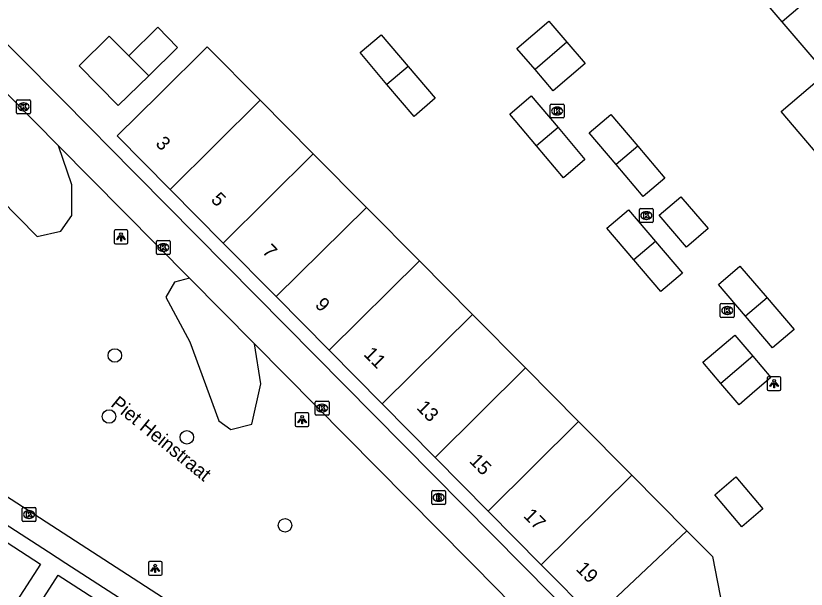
# Model space of a CAD drawing. Extents: x 160379 to 161131, y 383940 to 384849.
# Drawn here: x 160708.7 to 160765.9, y 384576.8 to 384618.3 of the extents above; entities that cross this region are included whole.
import ezdxf

# ---------------------------------------------------------------- set-up
doc = ezdxf.new("R2010")
doc.units = 0
for name, color, linetype in [('IMGEO_Boom', 7, 'Continuous'), ('IMGEO_Brandkraan', 7, 'Continuous'), ('IMGEO_Groenvoorziening', 7, 'Continuous'), ('IMGEO_Kolk', 7, 'Continuous'), ('IMGEO_Lichtpunt', 7, 'Continuous'), ('IMGEO_Openbare_ruimte_label', 7, 'Continuous'), ('IMGEO_Pand', 7, 'Continuous'), ('IMGEO_Pand_nummerreeks', 7, 'Continuous'), ('IMGEO_Voetgangersgebied_open', 7, 'Continuous')]:
    doc.layers.add(name, color=color, linetype=linetype)

msp = doc.modelspace()

# ---------------------------------------------------------------- linework, layer by layer
at = {"layer": 'IMGEO_Boom'}
for centre in [(160715.854, 384593.757), (160715.439, 384589.341), (160721.065, 384587.835), (160728.176, 384581.465)]:
    msp.add_circle(centre, 0.489, dxfattribs=at)
at = {"layer": 'IMGEO_Brandkraan'}
for p, q in [((160738.796, 384583.058), (160738.796, 384583.91)), ((160738.871, 384583.984), (160739.723, 384583.984)), ((160739.284, 384583.764), (160739.309, 384583.764)), ((160739.797, 384583.91), (160739.797, 384583.058)), ((160739.723, 384582.984), (160738.871, 384582.984)), ((160739.307, 384583.204), (160739.282, 384583.204))]:
    msp.add_line(p, q, dxfattribs=at)
for points in [[(160738.796, 384583.058), (160738.796, 384583.91)], [(160738.871, 384583.984), (160739.723, 384583.984)], [(160739.144, 384583.684), (160739.144, 384583.284), (160739.357, 384583.284)], [(160739.375, 384583.684), (160739.144, 384583.684)], [(160739.323, 384583.603), (160739.269, 384583.603), (160739.269, 384583.527)], [(160739.797, 384583.91), (160739.797, 384583.058)], [(160739.723, 384582.984), (160738.871, 384582.984)], [(160739.269, 384583.527), (160739.322, 384583.527)], [(160739.331, 384583.451), (160739.269, 384583.451), (160739.269, 384583.37)], [(160739.269, 384583.37), (160739.331, 384583.37)]]:
    msp.add_lwpolyline(points, dxfattribs=at)
for centre, radius, start, end in [((160738.873, 384583.908), 0.0765, 91.552, 178.448), ((160738.873, 384583.908), 0.0765, 91.552, 178.448), ((160739.324, 384583.565), 0.0379, 267.8285, 90.9355), ((160739.379, 384583.539), 0.145, 59.4692, 91.5367), ((160739.404, 384583.586), 0.0922, 285.5137, 58.1501), ((160739.721, 384583.908), 0.0765, 1.552, 88.448), ((160739.721, 384583.908), 0.0765, 1.552, 88.448), ((160738.873, 384583.06), 0.0765, 181.552, 268.448), ((160738.873, 384583.06), 0.0765, 181.552, 268.448), ((160739.332, 384583.41), 0.0404, 269.8759, 90.5077), ((160739.363, 384583.535), 0.251, 268.6676, 293.5347), ((160739.409, 384583.394), 0.105, 301.3115, 78.989), ((160739.721, 384583.06), 0.0765, 271.552, 358.448), ((160739.721, 384583.06), 0.0765, 271.552, 358.448)]:
    msp.add_arc(centre, radius, start, end, dxfattribs=at)
for centre, major_axis, ratio, start_param, end_param in [((160739.283, 384583.484), (-0.387, 0.002), 0.722429, 4.712389, 7.853982), ((160739.308, 384583.484), (-0.39, 0.002), 0.717154, 1.570796, 4.712389)]:
    msp.add_ellipse(centre, major_axis=major_axis, ratio=ratio, start_param=start_param, end_param=end_param, dxfattribs=at)
at = {"layer": 'IMGEO_Groenvoorziening'}
for points in [[(160699.59, 384611.514), (160701.271, 384608.535), (160703.61, 384607.511), (160707.527, 384605.097), (160710.224, 384602.36), (160711.951, 384602.741), (160712.738, 384603.874), (160712.736, 384606.095), (160711.786, 384608.924)], [(160721.26, 384599.354), (160720.165, 384599.054), (160719.537, 384597.985), (160721.297, 384594.737), (160723.391, 384589.033), (160724.263, 384588.408), (160725.779, 384588.784), (160726.437, 384591.692), (160725.963, 384594.603)]]:
    msp.add_lwpolyline(points, dxfattribs=at)
at = {"layer": 'IMGEO_Kolk'}
for p, q in [((160708.746, 384611.318), (160708.746, 384612.17)), ((160708.821, 384612.244), (160709.673, 384612.244)), ((160709.747, 384612.17), (160709.747, 384611.318)), ((160709.234, 384612.024), (160709.259, 384612.024)), ((160747.372, 384611.012), (160747.372, 384611.864)), ((160747.447, 384611.938), (160748.299, 384611.938)), ((160747.86, 384611.718), (160747.885, 384611.718)), ((160748.373, 384611.864), (160748.373, 384611.012)), ((160709.673, 384611.244), (160708.821, 384611.244)), ((160709.257, 384611.464), (160709.232, 384611.464)), ((160747.883, 384611.158), (160747.858, 384611.158)), ((160748.299, 384610.938), (160747.447, 384610.938)), ((160753.829, 384603.451), (160753.829, 384604.303)), ((160753.904, 384604.377), (160754.756, 384604.377)), ((160754.317, 384604.157), (160754.342, 384604.157)), ((160754.83, 384604.303), (160754.83, 384603.451)), ((160754.34, 384603.597), (160754.315, 384603.597)), ((160754.756, 384603.377), (160753.904, 384603.377)), ((160718.863, 384601.136), (160718.863, 384601.988)), ((160718.938, 384602.062), (160719.79, 384602.062)), ((160719.864, 384601.988), (160719.864, 384601.136)), ((160719.374, 384601.282), (160719.349, 384601.282)), ((160719.351, 384601.842), (160719.376, 384601.842)), ((160719.79, 384601.062), (160718.938, 384601.062)), ((160759.684, 384596.582), (160759.684, 384597.434)), ((160759.759, 384597.508), (160760.611, 384597.508)), ((160760.172, 384597.288), (160760.197, 384597.288)), ((160760.685, 384597.434), (160760.685, 384596.582)), ((160760.195, 384596.728), (160760.17, 384596.728)), ((160760.611, 384596.508), (160759.759, 384596.508)), ((160730.436, 384590.443), (160731.288, 384590.443)), ((160730.361, 384589.517), (160730.361, 384590.369)), ((160730.849, 384590.223), (160730.874, 384590.223)), ((160731.362, 384590.369), (160731.362, 384589.517)), ((160731.288, 384589.443), (160730.436, 384589.443)), ((160730.872, 384589.663), (160730.847, 384589.663)), ((160709.148, 384581.825), (160709.148, 384582.677)), ((160709.223, 384582.751), (160710.075, 384582.751)), ((160709.636, 384582.531), (160709.661, 384582.531)), ((160710.149, 384582.677), (160710.149, 384581.825)), ((160709.659, 384581.971), (160709.634, 384581.971)), ((160710.075, 384581.751), (160709.223, 384581.751))]:
    msp.add_line(p, q, dxfattribs=at)
for points in [[(160708.746, 384611.318), (160708.746, 384612.17)], [(160708.821, 384612.244), (160709.673, 384612.244)], [(160709.747, 384612.17), (160709.747, 384611.318)], [(160709.067, 384611.944), (160709.19, 384611.944), (160709.19, 384611.793), (160709.32, 384611.944), (160709.484, 384611.944), (160709.338, 384611.793), (160709.491, 384611.544), (160709.339, 384611.544), (160709.254, 384611.708), (160709.19, 384611.641), (160709.19, 384611.544), (160709.067, 384611.544), (160709.067, 384611.944)], [(160747.372, 384611.012), (160747.372, 384611.864)], [(160747.447, 384611.938), (160748.299, 384611.938)], [(160747.693, 384611.638), (160747.816, 384611.638), (160747.816, 384611.487), (160747.946, 384611.638), (160748.11, 384611.638), (160747.964, 384611.487), (160748.117, 384611.238), (160747.965, 384611.238), (160747.88, 384611.402), (160747.816, 384611.335), (160747.816, 384611.238), (160747.693, 384611.238), (160747.693, 384611.638)], [(160748.373, 384611.864), (160748.373, 384611.012)], [(160709.673, 384611.244), (160708.821, 384611.244)], [(160748.299, 384610.938), (160747.447, 384610.938)], [(160753.829, 384603.451), (160753.829, 384604.303)], [(160753.904, 384604.377), (160754.756, 384604.377)], [(160754.83, 384604.303), (160754.83, 384603.451)], [(160754.15, 384604.077), (160754.273, 384604.077), (160754.273, 384603.926), (160754.403, 384604.077), (160754.567, 384604.077), (160754.421, 384603.926), (160754.574, 384603.677), (160754.422, 384603.677), (160754.337, 384603.841), (160754.273, 384603.774), (160754.273, 384603.677), (160754.15, 384603.677), (160754.15, 384604.077)], [(160754.756, 384603.377), (160753.904, 384603.377)], [(160718.863, 384601.136), (160718.863, 384601.988)], [(160718.938, 384602.062), (160719.79, 384602.062)], [(160719.864, 384601.988), (160719.864, 384601.136)], [(160719.184, 384601.762), (160719.307, 384601.762), (160719.307, 384601.611), (160719.437, 384601.762), (160719.601, 384601.762), (160719.455, 384601.611), (160719.608, 384601.362), (160719.456, 384601.362), (160719.371, 384601.526), (160719.307, 384601.459), (160719.307, 384601.362), (160719.184, 384601.362), (160719.184, 384601.762)], [(160719.79, 384601.062), (160718.938, 384601.062)], [(160759.684, 384596.582), (160759.684, 384597.434)], [(160759.759, 384597.508), (160760.611, 384597.508)], [(160760.685, 384597.434), (160760.685, 384596.582)], [(160760.005, 384597.208), (160760.128, 384597.208), (160760.128, 384597.057), (160760.258, 384597.208), (160760.422, 384597.208), (160760.276, 384597.057), (160760.429, 384596.808), (160760.277, 384596.808), (160760.192, 384596.972), (160760.128, 384596.905), (160760.128, 384596.808), (160760.005, 384596.808), (160760.005, 384597.208)], [(160760.611, 384596.508), (160759.759, 384596.508)], [(160730.436, 384590.443), (160731.288, 384590.443)], [(160730.361, 384589.517), (160730.361, 384590.369)], [(160730.682, 384590.143), (160730.805, 384590.143), (160730.805, 384589.992), (160730.935, 384590.143), (160731.099, 384590.143), (160730.953, 384589.992), (160731.106, 384589.743), (160730.954, 384589.743), (160730.869, 384589.907), (160730.805, 384589.84), (160730.805, 384589.743), (160730.682, 384589.743), (160730.682, 384590.143)], [(160731.362, 384590.369), (160731.362, 384589.517)], [(160731.288, 384589.443), (160730.436, 384589.443)], [(160709.148, 384581.825), (160709.148, 384582.677)], [(160709.223, 384582.751), (160710.075, 384582.751)], [(160709.469, 384582.451), (160709.592, 384582.451), (160709.592, 384582.3), (160709.722, 384582.451), (160709.886, 384582.451), (160709.74, 384582.3), (160709.893, 384582.051), (160709.741, 384582.051), (160709.656, 384582.215), (160709.592, 384582.148), (160709.592, 384582.051), (160709.469, 384582.051), (160709.469, 384582.451)], [(160710.149, 384582.677), (160710.149, 384581.825)], [(160710.075, 384581.751), (160709.223, 384581.751)]]:
    msp.add_lwpolyline(points, dxfattribs=at)
for centre, start, end in [((160708.823, 384612.168), 91.552, 178.448), ((160708.823, 384612.168), 91.552, 178.448), ((160709.671, 384612.168), 1.552, 88.448), ((160709.671, 384612.168), 1.552, 88.448), ((160747.449, 384611.862), 91.552, 178.448), ((160747.449, 384611.862), 91.552, 178.448), ((160748.297, 384611.862), 1.552, 88.448), ((160748.297, 384611.862), 1.552, 88.448), ((160708.823, 384611.32), 181.552, 268.448), ((160708.823, 384611.32), 181.552, 268.448), ((160709.671, 384611.32), 271.552, 358.448), ((160709.671, 384611.32), 271.552, 358.448), ((160747.449, 384611.014), 181.552, 268.448), ((160747.449, 384611.014), 181.552, 268.448), ((160748.297, 384611.014), 271.552, 358.448), ((160748.297, 384611.014), 271.552, 358.448), ((160753.906, 384604.301), 91.552, 178.448), ((160753.906, 384604.301), 91.552, 178.448), ((160754.754, 384604.301), 1.552, 88.448), ((160754.754, 384604.301), 1.552, 88.448), ((160753.906, 384603.453), 181.552, 268.448), ((160753.906, 384603.453), 181.552, 268.448), ((160754.754, 384603.453), 271.552, 358.448), ((160754.754, 384603.453), 271.552, 358.448), ((160718.94, 384601.986), 91.552, 178.448), ((160718.94, 384601.986), 91.552, 178.448), ((160719.788, 384601.986), 1.552, 88.448), ((160719.788, 384601.986), 1.552, 88.448), ((160718.94, 384601.138), 181.552, 268.448), ((160718.94, 384601.138), 181.552, 268.448), ((160719.788, 384601.138), 271.552, 358.448), ((160719.788, 384601.138), 271.552, 358.448), ((160759.761, 384597.432), 91.552, 178.448), ((160759.761, 384597.432), 91.552, 178.448), ((160760.609, 384597.432), 1.552, 88.448), ((160760.609, 384597.432), 1.552, 88.448), ((160759.761, 384596.584), 181.552, 268.448), ((160759.761, 384596.584), 181.552, 268.448), ((160760.609, 384596.584), 271.552, 358.448), ((160760.609, 384596.584), 271.552, 358.448), ((160730.438, 384590.367), 91.552, 178.448), ((160730.438, 384590.367), 91.552, 178.448), ((160731.286, 384590.367), 1.552, 88.448), ((160731.286, 384590.367), 1.552, 88.448), ((160730.438, 384589.519), 181.552, 268.448), ((160730.438, 384589.519), 181.552, 268.448), ((160731.286, 384589.519), 271.552, 358.448), ((160731.286, 384589.519), 271.552, 358.448), ((160709.225, 384582.675), 91.552, 178.448), ((160709.225, 384582.675), 91.552, 178.448), ((160710.073, 384582.675), 1.552, 88.448), ((160710.073, 384582.675), 1.552, 88.448), ((160709.225, 384581.827), 181.552, 268.448), ((160709.225, 384581.827), 181.552, 268.448), ((160710.073, 384581.827), 271.552, 358.448), ((160710.073, 384581.827), 271.552, 358.448)]:
    msp.add_arc(centre, 0.0765, start, end, dxfattribs=at)
for centre, major_axis, ratio, start_param, end_param in [((160709.233, 384611.744), (-0.387, 0.002), 0.722429, 4.712389, 7.853982), ((160709.258, 384611.744), (-0.39, 0.002), 0.717154, 1.570796, 4.712389), ((160747.859, 384611.438), (-0.387, 0.002), 0.722429, 4.712389, 7.853982), ((160747.884, 384611.438), (-0.39, 0.002), 0.717154, 1.570796, 4.712389), ((160754.316, 384603.877), (-0.387, 0.002), 0.722429, 4.712389, 7.853982), ((160754.341, 384603.877), (-0.39, 0.002), 0.717154, 1.570796, 4.712389), ((160719.35, 384601.562), (-0.387, 0.002), 0.722429, 4.712389, 7.853982), ((160719.375, 384601.562), (-0.39, 0.002), 0.717154, 1.570796, 4.712389), ((160760.171, 384597.008), (-0.387, 0.002), 0.722429, 4.712389, 7.853982), ((160760.196, 384597.008), (-0.39, 0.002), 0.717154, 1.570796, 4.712389), ((160730.848, 384589.943), (-0.387, 0.002), 0.722429, 4.712389, 7.853982), ((160730.873, 384589.943), (-0.39, 0.002), 0.717154, 1.570796, 4.712389), ((160709.635, 384582.251), (-0.387, 0.002), 0.722429, 4.712389, 7.853982), ((160709.66, 384582.251), (-0.39, 0.002), 0.717154, 1.570796, 4.712389)]:
    msp.add_ellipse(centre, major_axis=major_axis, ratio=ratio, start_param=start_param, end_param=end_param, dxfattribs=at)
at = {"layer": 'IMGEO_Lichtpunt'}
for p, q in [((160715.805, 384602.738), (160715.805, 384601.931)), ((160715.805, 384602.738), (160715.805, 384601.931)), ((160716.707, 384602.833), (160715.899, 384602.833)), ((160716.707, 384602.833), (160715.899, 384602.833)), ((160716.801, 384601.931), (160716.801, 384602.738)), ((160716.801, 384601.931), (160716.801, 384602.738)), ((160715.899, 384601.837), (160716.707, 384601.837)), ((160715.899, 384601.837), (160716.707, 384601.837)), ((160763.077, 384592.126), (160763.077, 384591.319)), ((160763.077, 384592.126), (160763.077, 384591.319)), ((160763.979, 384592.221), (160763.171, 384592.221)), ((160763.979, 384592.221), (160763.171, 384592.221)), ((160764.073, 384591.319), (160764.073, 384592.126)), ((160764.073, 384591.319), (160764.073, 384592.126)), ((160763.171, 384591.225), (160763.979, 384591.225)), ((160763.171, 384591.225), (160763.979, 384591.225)), ((160728.914, 384589.512), (160728.914, 384588.705)), ((160728.914, 384589.512), (160728.914, 384588.705)), ((160729.816, 384589.607), (160729.008, 384589.607)), ((160729.816, 384589.607), (160729.008, 384589.607)), ((160729.91, 384588.705), (160729.91, 384589.512)), ((160729.91, 384588.705), (160729.91, 384589.512)), ((160729.008, 384588.611), (160729.816, 384588.611)), ((160729.008, 384588.611), (160729.816, 384588.611)), ((160718.284, 384578.753), (160718.284, 384577.946)), ((160718.284, 384578.753), (160718.284, 384577.946)), ((160719.186, 384578.848), (160718.378, 384578.848)), ((160719.186, 384578.848), (160718.378, 384578.848)), ((160719.28, 384577.946), (160719.28, 384578.753)), ((160719.28, 384577.946), (160719.28, 384578.753)), ((160718.378, 384577.852), (160719.186, 384577.852)), ((160718.378, 384577.852), (160719.186, 384577.852))]:
    msp.add_line(p, q, dxfattribs=at)
for points in [[(160716.179, 384602.402), (160716.218, 384602.374), (160716.03, 384602.112), (160715.992, 384602.139), (160716.179, 384602.402)], [(160716.281, 384602.354), (160716.328, 384602.354), (160716.328, 384602.032), (160716.281, 384602.032), (160716.281, 384602.354)], [(160716.391, 384602.374), (160716.429, 384602.401), (160716.616, 384602.139), (160716.577, 384602.111), (160716.391, 384602.374)], [(160763.451, 384591.79), (160763.49, 384591.762), (160763.302, 384591.5), (160763.264, 384591.527), (160763.451, 384591.79)], [(160763.553, 384591.742), (160763.6, 384591.742), (160763.6, 384591.42), (160763.553, 384591.42), (160763.553, 384591.742)], [(160763.663, 384591.762), (160763.701, 384591.789), (160763.888, 384591.527), (160763.849, 384591.499), (160763.663, 384591.762)], [(160729.288, 384589.176), (160729.327, 384589.148), (160729.139, 384588.886), (160729.101, 384588.913), (160729.288, 384589.176)], [(160729.39, 384589.128), (160729.437, 384589.128), (160729.437, 384588.806), (160729.39, 384588.806), (160729.39, 384589.128)], [(160729.5, 384589.148), (160729.538, 384589.175), (160729.725, 384588.913), (160729.686, 384588.885), (160729.5, 384589.148)], [(160718.658, 384578.417), (160718.697, 384578.389), (160718.509, 384578.127), (160718.471, 384578.154), (160718.658, 384578.417)], [(160718.87, 384578.389), (160718.908, 384578.416), (160719.095, 384578.154), (160719.056, 384578.126), (160718.87, 384578.389)], [(160718.76, 384578.369), (160718.807, 384578.369), (160718.807, 384578.047), (160718.76, 384578.047), (160718.76, 384578.369)]]:
    msp.add_lwpolyline(points, dxfattribs=at)
for centre in [(160716.304, 384602.536), (160763.576, 384591.924), (160729.413, 384589.31), (160718.783, 384578.551)]:
    msp.add_circle(centre, 0.0994, dxfattribs=at)
for centre, start, end in [((160715.899, 384602.738), 90, 180), ((160715.899, 384602.738), 90, 180), ((160716.707, 384602.738), 0, 90), ((160716.707, 384602.738), 0, 90), ((160715.899, 384601.931), 180, 270), ((160715.899, 384601.931), 180, 270), ((160716.707, 384601.931), 270, 0), ((160716.707, 384601.931), 270, 360), ((160763.171, 384592.126), 90, 180), ((160763.171, 384592.126), 90, 180), ((160763.979, 384592.126), 0, 90), ((160763.979, 384592.126), 0, 90), ((160763.171, 384591.319), 180, 270), ((160763.171, 384591.319), 180, 270), ((160763.979, 384591.319), 270, 0), ((160763.979, 384591.319), 270, 360), ((160729.008, 384589.512), 90, 180), ((160729.008, 384589.512), 90, 180), ((160729.816, 384589.512), 0, 90), ((160729.816, 384589.512), 0, 90), ((160729.008, 384588.705), 180, 270), ((160729.008, 384588.705), 180, 270), ((160729.816, 384588.705), 270, 0), ((160729.816, 384588.705), 270, 360), ((160718.378, 384578.753), 90, 180), ((160718.378, 384578.753), 90, 180), ((160719.186, 384578.753), 0, 90), ((160719.186, 384578.753), 0, 90), ((160718.378, 384577.946), 180, 270), ((160718.378, 384577.946), 180, 270), ((160719.186, 384577.946), 270, 0), ((160719.186, 384577.946), 270, 360)]:
    msp.add_arc(centre, 0.0946, start, end, dxfattribs=at)
at = {"layer": 'IMGEO_Pand'}
for points in [[(160771.144, 384623.858), (160764.164, 384617.895)], [(160764.164, 384617.895), (160760.992, 384621.608)], [(160746.278, 384614.432), (160744.967, 384615.96), (160747.272, 384617.93), (160748.582, 384616.409)], [(160767.337, 384614.183), (160764.164, 384617.895)], [(160716.859, 384615.44), (160718.967, 384617.515), (160720.405, 384616.026), (160718.308, 384613.978)], [(160718.308, 384613.978), (160716.107, 384611.828), (160713.265, 384614.708), (160715.451, 384616.86), (160716.859, 384615.44)], [(160735.557, 384613.361), (160733.604, 384615.665), (160735.13, 384616.962), (160737.087, 384614.663)], [(160748.582, 384616.409), (160749.904, 384614.874), (160747.588, 384612.904), (160746.278, 384614.432)], [(160748.582, 384616.409), (160746.278, 384614.432)], [(160719.863, 384605.769), (160716.028, 384609.647), (160719.085, 384612.663), (160722.549, 384616.082), (160726.383, 384612.216)], [(160718.308, 384613.978), (160716.859, 384615.44)], [(160737.087, 384614.663), (160739.043, 384612.364), (160737.515, 384611.052), (160735.557, 384613.361)], [(160737.087, 384614.663), (160735.557, 384613.361)], [(160770.509, 384610.47), (160767.258, 384607.692), (160764.086, 384611.405), (160767.337, 384614.183)], [(160726.383, 384612.216), (160719.863, 384605.769)], [(160726.383, 384612.216), (160730.224, 384608.344)], [(160746.387, 384608.916), (160744.444, 384611.216), (160746.002, 384612.544), (160747.95, 384610.236)], [(160752.148, 384607.561), (160750.197, 384609.852), (160751.77, 384611.183), (160753.715, 384608.887)], [(160747.95, 384610.236), (160749.89, 384607.937), (160748.329, 384606.615), (160746.387, 384608.916)], [(160747.95, 384610.236), (160746.387, 384608.916)], [(160753.715, 384608.887), (160755.659, 384606.591), (160754.102, 384605.266), (160752.148, 384607.561)], [(160753.715, 384608.887), (160752.148, 384607.561)], [(160730.224, 384608.344), (160723.699, 384601.891)], [(160730.224, 384608.344), (160734.065, 384604.471)], [(160723.699, 384601.891), (160719.863, 384605.769)], [(160757.237, 384601.601), (160755.262, 384603.909), (160756.827, 384605.239), (160758.801, 384602.944), (160757.237, 384601.601)], [(160734.065, 384604.471), (160727.534, 384598.012)], [(160734.065, 384604.471), (160737.906, 384600.598)], [(160753.425, 384600.664), (160751.467, 384602.955), (160753.035, 384604.29), (160754.989, 384601.996)], [(160727.534, 384598.012), (160723.699, 384601.891)], [(160754.989, 384601.996), (160756.943, 384599.702), (160755.374, 384598.382), (160753.425, 384600.664)], [(160754.989, 384601.996), (160753.425, 384600.664)], [(160737.906, 384600.598), (160731.369, 384594.134)], [(160737.906, 384600.598), (160741.747, 384596.726)], [(160761.511, 384596.596), (160759.548, 384598.892), (160761.105, 384600.22), (160763.068, 384597.931)], [(160731.369, 384594.134), (160727.534, 384598.012)], [(160763.068, 384597.931), (160765.031, 384595.641), (160763.472, 384594.303), (160761.511, 384596.596)], [(160763.068, 384597.931), (160761.511, 384596.596)], [(160741.747, 384596.726), (160735.205, 384590.256)], [(160741.747, 384596.726), (160745.588, 384592.853)], [(160759.733, 384591.728), (160758.413, 384593.263), (160760.742, 384595.23), (160762.047, 384593.696)], [(160735.205, 384590.256), (160731.369, 384594.134)], [(160762.047, 384593.696), (160763.351, 384592.163), (160762.186, 384591.163), (160761.054, 384590.192), (160759.733, 384591.728)], [(160762.047, 384593.696), (160759.733, 384591.728)], [(160745.588, 384592.853), (160739.04, 384586.378)], [(160745.588, 384592.853), (160749.429, 384588.98)], [(160739.04, 384586.378), (160735.205, 384590.256)], [(160749.429, 384588.98), (160742.875, 384582.499)], [(160749.429, 384588.98), (160753.269, 384585.108)], [(160742.875, 384582.499), (160739.04, 384586.378)], [(160753.269, 384585.108), (160746.711, 384578.621)], [(160753.269, 384585.108), (160757.263, 384581.081)], [(160762.775, 384582.671), (160761.239, 384581.355), (160759.279, 384583.664), (160760.809, 384584.964), (160762.775, 384582.671)], [(160746.711, 384578.621), (160742.875, 384582.499)], [(160706.03, 384581.538), (160710.479, 384578.651), (160705.488, 384570.959), (160701.041, 384573.844)], [(160757.263, 384581.081), (160750.546, 384574.743)], [(160757.263, 384581.081), (160759.108, 384579.223), (160760.561, 384571.796)], [(160750.546, 384574.743), (160746.711, 384578.621)], [(160711.594, 384567.052), (160710.943, 384566.044), (160709.378, 384563.379), (160704.454, 384566.424), (160706.129, 384569.152), (160706.762, 384570.133), (160711.753, 384577.864), (160716.569, 384574.755)]]:
    msp.add_lwpolyline(points, dxfattribs=at)
at = {"layer": 'IMGEO_Voetgangersgebied_open'}
for points in [[(160759.828, 384522.305), (160755.906, 384542.287), (160755.616, 384543.763), (160752.301, 384560.653), (160749.625, 384574.277), (160715.318, 384608.946), (160714.28, 384609.995), (160704.012, 384620.371), (160696.715, 384627.735), (160696.648, 384627.802)], [(160705.029, 384615.75), (160711.786, 384608.924)], [(160711.786, 384608.924), (160721.26, 384599.354)], [(160670.645, 384605.594), (160678.608, 384600.475), (160690.284, 384592.968), (160711.06, 384579.547), (160712.316, 384578.736), (160741.675, 384559.771), (160742.043, 384557.929), (160749.399, 384520.262)], [(160721.26, 384599.354), (160725.963, 384594.603)], [(160725.963, 384594.603), (160743.669, 384576.716), (160744.754, 384575.566), (160746.227, 384573.82)], [(160733.288, 384567.211), (160697.299, 384590.465)]]:
    msp.add_lwpolyline(points, dxfattribs=at)

# ---------------------------------------------------------------- texts
at = {"layer": 'IMGEO_Openbare_ruimte_label'}
msp.add_text('Piet Heinstraat', height=1, rotation=320.8839, dxfattribs=at).set_placement((160715.498, 384590.132))
at = {"layer": 'IMGEO_Pand_nummerreeks'}
for s, p in [('3', (160718.75, 384609.028)), ('5', (160722.76, 384604.973)), ('7', (160726.469, 384601.222)), ('9', (160730.288, 384597.36)), ('11', (160733.819, 384593.791)), ('13', (160737.639, 384589.928)), ('15', (160741.457, 384586.067)), ('17', (160745.377, 384582.104)), ('19', (160749.178, 384578.26))]:
    msp.add_text(s, height=1, rotation=314.679, dxfattribs=at).set_placement(p)

doc.saveas('drawing.dxf')
